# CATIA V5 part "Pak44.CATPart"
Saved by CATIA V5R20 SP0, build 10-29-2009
Part number: Pak44
Bounding box of the stored display mesh (mm): x -250 to 250, y -7480 to 550, z -175 to 250
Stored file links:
  E:\新建文件夹 (2)\Pak44.CATPart
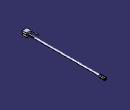
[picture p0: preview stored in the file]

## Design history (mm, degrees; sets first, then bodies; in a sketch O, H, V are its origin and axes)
Body1 (main body)
  Sketch1 on zx-plane, origin (0, 0, 0), H (-1, 0, 0), V (0, 0, 1)
    circle A1 centre (0, 0) radius 64
    circle A2 centre (0, 0) radius 130
    radius A1 = 64
    radius A2 = 130
  Pad1: profile Sketch1, direction (0, 1, 0), length 550
  Body2
    Sketch2 on yz-plane, origin (0, 0, 0), H (0, 1, 0), V (0, 0, 1)
      circle A1 centre (50, 0) radius 10
      circle A2 centre (20, 0) radius 10
      circle A3 centre (110, 0) radius 10
      circle A4 centre (80, 0) radius 10
      circle A5 centre (170, 0) radius 10
      circle A6 centre (140, 0) radius 10
      circle A7 centre (350, 0) radius 10
      circle A8 centre (290, 0) radius 10
      circle A9 centre (200, 0) radius 10
      circle A10 centre (230, 0) radius 10
      circle A11 centre (260, 0) radius 10
      circle A12 centre (320, 0) radius 10
      circle A13 centre (380, 0) radius 10
      circle A14 centre (410, 0) radius 10
      circle A15 centre (440, 0) radius 10
      circle A16 centre (470, 0) radius 10
      circle A17 centre (500, 0) radius 10
      circle A18 centre (530, 0) radius 10
    Pad2: profile Sketch2, direction (1, 0, 0), length 550, mirrored extent
  Remove1: tool Body2
  Body3
    Sketch3 on xy-plane, origin (0, 0, 0), H (1, 0, 0), V (0, 1, 0)
      circle A1 centre (0, 20) radius 10
      circle A2 centre (0, 50) radius 10
      circle A3 centre (0, 80) radius 0
      circle A4 centre (0, 80) radius 10
      point P1 (0, 70)
      circle A5 centre (0, 110) radius 10
      point P2 (0, 100)
      circle A6 centre (0, 140) radius 10
      circle A7 centre (0, 170) radius 10
      circle A8 centre (0, 200) radius 10
      circle A9 centre (0, 230) radius 10
      point P3 (0, 240)
      circle A10 centre (0, 260) radius 10
      point P4 (0, 270)
      circle A11 centre (0, 290) radius 10
      point P5 (0, 300)
      circle A12 centre (0, 320) radius 10
      circle A13 centre (0, 350) radius 10
      point P6 (0, 340)
      circle A14 centre (0, 380) radius 10
      point P7 (0, 370)
      circle A15 centre (0, 410) radius 10
      point P8 (0, 400)
      circle A16 centre (0, 440) radius 10
      point P9 (0, 430)
      circle A17 centre (0, 470) radius 10
      circle A18 centre (0, 500) radius 10
      point P10 (0, 490)
      circle A19 centre (0, 530) radius 10
    Pad3: profile Sketch3, direction (0, 0, 1), length 550, mirrored extent
  Remove2: tool Body3
  Body4
    Plane1: type Angle, RefPlane yz-plane, Direction Y axis, Angle 45
    Sketch4 on Plane1, origin (0, 0, 0), H (0.7071, 0, 0.7071), V (0, 1, 0)
      circle A1 centre (0, 20) radius 10
      circle A2 centre (0, 50) radius 10
      circle A3 centre (0, 80) radius 0
      circle A4 centre (0, 80) radius 10
      point P1 (0, 70)
      circle A5 centre (0, 110) radius 10
      point P2 (0, 100)
      circle A6 centre (0, 140) radius 10
      circle A7 centre (0, 170) radius 10
      circle A8 centre (0, 200) radius 10
      circle A9 centre (0, 230) radius 10
      point P3 (0, 240)
      circle A10 centre (0, 260) radius 10
      point P4 (0, 270)
      circle A11 centre (0, 290) radius 10
      point P5 (0, 300)
      circle A12 centre (0, 320) radius 10
      circle A13 centre (0, 350) radius 10
      point P6 (0, 340)
      circle A14 centre (0, 380) radius 10
      point P7 (0, 370)
      circle A15 centre (0, 410) radius 10
      point P8 (0, 400)
      circle A16 centre (0, 440) radius 10
      point P9 (0, 430)
      circle A17 centre (0, 470) radius 10
      circle A18 centre (0, 500) radius 10
      point P10 (0, 490)
      circle A19 centre (0, 530) radius 10
    Pad4: profile Sketch4, direction (-0.7071, 0, 0.7071), length 550, mirrored extent
  Remove3: tool Body4
  Body5
    Plane2: type Angle, RefPlane yz-plane, Direction Y axis, Angle 135
    Sketch5 on Plane2, origin (0, 0, 0), H (0.7071, 0, -0.7071), V (0, 1, 0)
      circle A1 centre (0, 20) radius 10
      circle A2 centre (0, 50) radius 10
      circle A3 centre (0, 80) radius 0
      circle A4 centre (0, 80) radius 10
      point P1 (0, 70)
      circle A5 centre (0, 110) radius 10
      point P2 (0, 100)
      circle A6 centre (0, 140) radius 10
      circle A7 centre (0, 170) radius 10
      circle A8 centre (0, 200) radius 10
      circle A9 centre (0, 230) radius 10
      point P3 (0, 240)
      circle A10 centre (0, 260) radius 10
      point P4 (0, 270)
      circle A11 centre (0, 290) radius 10
      point P5 (0, 300)
      circle A12 centre (0, 320) radius 10
      circle A13 centre (0, 350) radius 10
      point P6 (0, 340)
      circle A14 centre (0, 380) radius 10
      point P7 (0, 370)
      circle A15 centre (0, 410) radius 10
      point P8 (0, 400)
      circle A16 centre (0, 440) radius 10
      point P9 (0, 430)
      circle A17 centre (0, 470) radius 10
      circle A18 centre (0, 500) radius 10
      point P10 (0, 490)
      circle A19 centre (0, 530) radius 10
    Pad5: profile Sketch5, direction (0.7071, 0, 0.7071), length 550, mirrored extent
  Remove4: tool Body5
  Sketch6 on zx-plane, origin (0, 0, 0), H (-1, 0, 0), V (0, 0, 1)
    circle A1 centre (0, 0) radius 64
    reference projected circle E1 centre (0, 0) radius 64 from edge [end face of Pad1 | face of Pad1 from Sketch1.A1]
    circle A2 centre (0, 0) radius 92.1954
    radius A2 = 92.1954
    coincidence: A1 E1
  Pad6: profile Sketch6, direction (0, -1, 0), length 7040
  Sketch7 on end face of Pad6, origin (0, -7040, 0), H (1, 0, 0), V (0, 0, 1)
    line L1 (200, 175) -> (200, -175)
    line L2 (200, -175) -> (-200, -175)
    line L3 (-200, -175) -> (-200, -64)
    line L4 (-200, 175) -> (200, 175)
    arc A1 centre (0, 0) radius 64 from (0, -64) to (0, 64) ccw
    point P5 (0, 64)
    reference projected circle E1 centre (0, 0) radius 64 from edge [face of Pad6 from Sketch6.A1 | end face of Pad6]
    line L5 (0, 64) -> (-200, 64)
    line L6 (0, -64) -> (-200, -64)
    point P7 (0, -64)
    line L7 (-200, 64) -> (-200, 175)
    length L1 = 350
    length L4 = 400
    vertical: L1 V, L3 V, L7 V
    horizontal: L2 H, L4 H
    equidistance: L1 L3 O, L2 L4 O
    coincidence: P5 V, A1 E1, P7 V, L3 L7
    tangency: L5 A1, L6 A1
  Pad7: profile Sketch7, direction (0, -1, 0), length 440
  Sketch8 on end face of Pad6, origin (0, -7040, 0), H (1, 0, 0), V (0, 0, 1)
    line L1 (200, 175) -> (200, -175)
    line L2 (200, -175) -> (-200, -175)
    line L3 (-200, -175) -> (-200, 175)
    line L4 (-200, 175) -> (200, 175)
    circle A1 centre (0, 0) radius 64
    reference projected circle E1 centre (0, 0) radius 64 from edge [face of Pad6 | end face of Pad6]
    vertical: L1 V, L3 V
    horizontal: L2 H, L4 H
    equidistance: L1 L3 O, L2 L4 O
    coincidence: A1 E1
  Pad8: profile Sketch8, direction (0, -1, 0), length 200
  Sketch9 on face of Pad8, origin (0, -7040, 0), H (-1, 0, 0), V (0, 0, 1)
    point P1 (0, 170)
    circle A1 centre (-220, 220) radius 30
    point P4 (-170, 200)
    circle A2 centre (220, 220) radius 30
    point P5 (170, 200)
  Pad9: profile Sketch9, direction (0, 1, 0), length 700
  Sketch10 on face of Pad8, origin (0, -7040, 0), H (-1, 0, 0), V (0, 0, 1)
    line L1 (-200, 240) -> (200, 240)
    line L2 (200, 240) -> (200, 175)
    line L3 (200, 175) -> (-200, 175)
    line L4 (-200, 175) -> (-200, 240)
    reference projected line E1 (-200, 175) -> (200, 175) from edge [face of Pad8 | face of Pad7 from Sketch7.L4]
    horizontal: L1 H, L3 H
    vertical: L2 V, L4 V
    coincidence: L3 E1
  Pad10: profile Sketch10, direction (0, -1, 0), length 440
  Sketch11 on face of Pad10, origin (0, -7480, 0), H (1, 0, 0), V (0, 0, 1)
    point P1 (220, 240)
    line L1 (200, 240) -> (240, 240)
    line L2 (240, 240) -> (240, 64)
    line L3 (200, 64) -> (200, 240)
    point P4 (-200, 240)
    line L4 (-200, 240) -> (-240, 240)
    line L5 (-240, 240) -> (-240, 64)
    line L6 (-200, 64) -> (-240, 64)
    line L7 (-200, 64) -> (-200, 240)
    line L8 (200, 64) -> (240, 64)
    point P8 (200, 64)
    horizontal: L1 H, L4 H, L6 H, L8 H
    vertical: L2 V, L3 V, L5 V, L7 V
    coincidence: P4 L1, P8 L6
  Pad11: profile Sketch11, direction (0, 1, 0), length 440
